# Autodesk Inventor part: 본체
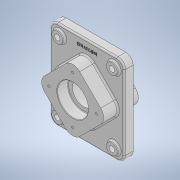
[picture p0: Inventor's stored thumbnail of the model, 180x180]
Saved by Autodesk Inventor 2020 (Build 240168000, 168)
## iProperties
Created: 2021-07
Part Number: 본체
Material: 일반
Document SubType Name: Modeling
Designer: Owner
Density: 1 g/cm^3
Appearance: 기본값
Mass: 808.432 g
Surface Area: 958.051 cm^2
Volume: 808.432 cm^3
Author: Owner
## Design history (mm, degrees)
sketch "스케치1"
  geometry: L1 (-75, 90)-(75, 90); L2 (75, 90)-(75, -90); L3 (75, -90)-(-75, -90); L4 (-75, -90)-(-75, 90); L5 (-75, 90)-(75, -90); L6 (75, 90)-(-75, -90); 1 further point
  constraints: 12 end point, 2 midpoint, 2 parallel, 1 horizontal, 1 perpendicular
  dimensions: "d0" = 150 distance of L2.end L3.end; "d1" = 180 distance of L1.end L2.end
extrude "돌출1" new body sketch "스케치1" stored distance "d2" = 18; taper "d3" = 0 deg
sketch "스케치2"
  geometry: L1 (0, 70.711)-(-70.711, 0); L2 (-70.711, 0)-(0, -70.711); L3 (0, -70.711)-(70.711, 0); L4 (70.711, 0)-(0, 70.711); L5 (75, -90)-(75, 90) reference; L6 (-75, 90)-(-75, -90) reference; L7 (-75, -90)-(75, -90) reference; 5 further points
  constraints: 8 end point, 4 midpoint, 2 horizontal alignment, 2 parallel, 2 perpendicular, 2 vertical alignment
  dimensions: "d4" = 100 distance of L2.end L3.end
extrude "돌출2" join sketch "스케치2" distance "d5" = 29; taper "d6" = 0 deg
fillet "모깎기1" dims "d7" = 20
fillet "모깎기2" dims "d8" = 3
sketch "스케치3"
  geometry: C1 r 31 at (0, 0); 1 further point
  constraints: 1 centre point, 1 coincident
  dimensions: "d9" = 62 diameter of C1
extrude "돌출3" cut sketch "스케치3" distance "d10" = 22; taper "d11" = 0 deg
sketch "스케치4"
  geometry: C1 r 22.5 at (0, 0); 1 further point
  constraints: 1 centre point, 1 coincident
  dimensions: "d12" = 45 diameter of C1
sketch "스케치5"
  geometry: L1 (0, 70.711)-(70.711, 0); L2 (70.711, 0)-(0, -70.711); L3 (0, -70.711)-(-70.711, 0); L4 (-70.711, 0)-(0, 70.711); L5 (75, -90)-(75, 90) reference; L6 (-75, 90)-(-75, -90) reference; L7 (75, 90)-(-75, 90) reference; L8 (-75, -90)-(75, -90) reference; 5 further points
  constraints: 8 end point, 4 midpoint, 2 horizontal alignment, 2 parallel, 2 vertical alignment, 1 perpendicular
  dimensions: "d13" = 100 distance of L3.end L1.start
extrude "돌출4" join sketch "스케치5" distance "d14" = 23; taper "d15" = 0 deg
extrude "돌출5" cut sketch "스케치4" distance "d16" = 26; taper "d17" = 0 deg
fillet "모깎기3" dims "d18" = 20
sketch "스케치6"
  geometry: C1 r 31 at (0, 0); 1 further point
  constraints: 1 centre point, 1 coincident
  dimensions: "d19" = 62 diameter of C1
extrude "돌출6" cut sketch "스케치6" distance "d20" = 22; taper "d21" = 0 deg
fillet "모깎기4" dims "d22" = 15
fillet "모깎기5" dims "d23" = 3
fillet "모깎기6" dims "d24" = 3
sketch "스케치7"
  geometry: L1 (-75, 75)-(-75, -75) reference; L2 (60, 90)-(-60, 90) reference; C1 r 11 at (-55, 70); C2 r 11 at (55, 70); 1 further point
  constraints: 2 centre point, 1 horizontal alignment
  dimensions: "d28" = 22 diameter of C1; "d29" = 22 diameter of C2; "d30" = 110 distance of C1.centre C2.centre; "d31" = 20 distance from line of L1 C1.centre; "d32" = 20 distance from line of L2 C1.centre
extrude "돌출7" join sketch "스케치7" distance "d33" = 5; taper "d34" = 0 deg
sketch "스케치8"
  geometry: C1 r 11 at (0, 0) reference; 2 further points
  constraints: 1 coincident
hole "구멍1" sketch "스케치8" at (0, 0) diameter "d35" = 11; stored, may be unused: countersink angle "d39" = 90 deg, drill point angle "d41" = 0 deg; dims "d36" = 6, "d37" = 4, "d38" = 2, "d40" = 23
sketch "스케치9"
  geometry: C1 r 11 at (0, 0) reference; 2 further points
  constraints: 1 coincident
hole "구멍2" sketch "스케치9" at (0, 0) diameter "d42" = 11; stored, may be unused: countersink angle "d46" = 90 deg, drill point angle "d48" = 0 deg; dims "d43" = 6, "d44" = 4, "d45" = 2, "d47" = 23
sketch "스케치10"
  geometry: C1 r 11 at (0, 0) reference; 2 further points
  constraints: 1 coincident
hole "구멍3" sketch "스케치10" at (0, 0) diameter "d49" = 11; stored, may be unused: countersink angle "d53" = 90 deg, drill point angle "d55" = 0 deg; dims "d50" = 6, "d51" = 4, "d52" = 2, "d54" = 23
sketch "스케치11"
  geometry: C1 r 11 at (0, 0) reference; 2 further points
  constraints: 1 coincident
hole "구멍4" sketch "스케치11" at (0, 0) diameter "d56" = 11; stored, may be unused: countersink angle "d60" = 90 deg, drill point angle "d62" = 0 deg; dims "d57" = 6, "d58" = 4, "d59" = 2, "d61" = 23
fillet "모깎기7" dims "d63" = 3
sketch "스케치12"
  geometry: 2 further points
  constraints: 1 vertical alignment
  dimensions: "d64" = 48 distance of point (0, 0) point (0, 48)
hole "구멍5" sketch "스케치12" at (0, 48) diameter "d65" = 4.917; stored, may be unused: countersink angle "d69" = 90 deg, drill point angle "d71" = 118 deg; dims "d66" = 10, "d67" = 4, "d68" = 2, "d70" = 13
sketch "스케치13"
  geometry: L1 (60, 90)-(-60, 90) reference; 2 further points
  constraints: 1 vertical alignment, 1 other
  dimensions: "d75" = 15 distance from line of L1 point (0, 75)
feature "엠보싱1" sketch "스케치13" dims "d0" = 150, "d1" = 180, "d76" = 0.5, "d77" = 0
fillet "모깎기8" dims "d78" = 1
chamfer "모따기1" distance "d79" = 1; stored, may be unused: second distance "d80" = 2, angle "d81" = 45 deg
sketch "스케치14"
  geometry: 2 further points
  constraints: 1 vertical alignment
  dimensions: "d82" = 48 distance of point (0, 0) point (0, 48)
hole "구멍6" sketch "스케치14" at (0, 48) diameter "d83" = 4.917; stored, may be unused: countersink angle "d87" = 90 deg, drill point angle "d89" = 118 deg; dims "d84" = 10, "d85" = 4, "d86" = 2, "d88" = 13
node "솔리드1"
mirror "미러1"
pattern_circular "원형 패턴1" dims angle "d73" = 360 deg
pattern_circular "원형 패턴2" dims angle "d91" = 360 deg
feature "A9D066F2-1C7D-4E18-AEED-F7BC21143FA4" dims "d35" = 11, "d36" = 6, "d37" = 4, "d38" = 2, "d39" = 90 deg, "d40" = 23, "d41" = 0
